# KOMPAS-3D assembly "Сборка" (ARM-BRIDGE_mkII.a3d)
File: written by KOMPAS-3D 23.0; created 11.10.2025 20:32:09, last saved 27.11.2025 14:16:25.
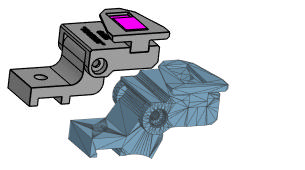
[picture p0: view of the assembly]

Document properties: Автор: ADMIN; Полное имя файла: D:\YandexDisk\Model\NVG\ARM mkII\ARM-BRIDGE mkII.a3d

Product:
- Component [detail]: Мост  | qty 1  | Масса: 0.115148; Автор: ADMIN; source file: Bridge Middle Body p3b.m3d
- Component [detail]: АРМ Л  | qty 1  | Масса: 0.072746; Автор: ADMIN; source file: ARM p2 p2b.m3d
- Component [detail]: АРМ П  | qty 1  | Масса: 0.072746; Автор: ADMIN; source file: ARM p2 p2b.m3d
- Component [detail]: АРМ  | qty 1  | Масса: 0.081709; Автор: ADMIN; source file: ARM Middle Body p3b.m3d
- Component [detail]: Лапа МНВ П  | qty 1  | Масса: 0.016505; Автор: ADMIN; source file: ARM p3 MNV.p1b.m3d
- Component [detail]: Wilcox_G24_Dovetail_modified  | qty 1  | Автор: ADMIN; source file: ..\ARM-MNV mk1\Wilcox_G24_Dovetail_modified.stl
- Component [detail]: katod_new_podog  | qty 1  | Автор: ADMIN; source file: ..\ARM-MNV mk1\katod_new_podog.stl
- Component [detail]: Wilcox_G24_arm  | qty 1  | Автор: ADMIN; source file: ..\ARM-MNV mk1\Wilcox_G24_arm.stl
- Component [detail]: Уплотнитель  | qty 1  | Масса: 0.003931; Автор: ADMIN; source file: ARM TPU Insert.m3d
- Component [detail]: Лапа МНВ Л  | qty 1  | Масса: 0.016505; Автор: ADMIN; source file: ARM p3 MNV.p1b.m3d
- Component [detail]: Деталь  | qty 1  | Масса: 0.030122; Автор: ADMIN; source file: Wilcox Adapter.m3d
- Component [detail]: (unnamed)  | qty 1  | Масса: 0.087098; Автор: ADMIN; source file: ARM p2+p3 MNV.m3d
- Part/product: Сборка
    Масса: 0.49651

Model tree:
1. Сечение:1

Referenced files in D:\YandexDisk\Model\NVG\ARM mkII\: Bridge Middle Body p3b.m3d, ARM p2 p2b.m3d, ARM Middle Body p3b.m3d, ARM p3 MNV.p1b.m3d, Wilcox Adapter.m3d, ARM TPU Insert.m3d, ARM p2+p3 MNV.m3d
Referenced files: >Деталь (локальная) 3.m3d, >Деталь (локальная) 4.m3d, >Деталь (локальная) 5.m3d
Referenced files in D:\YandexDisk\Model\NVG\ARM-MNV mk1\: Wilcox_G24_Dovetail_modified.stl, katod_new_podog.stl, Wilcox_G24_arm.stl
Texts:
  АРМ Л (1)
  АРМ П (2)
  Лапа МНВ П (1)
  Лапа МНВ Л (2)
